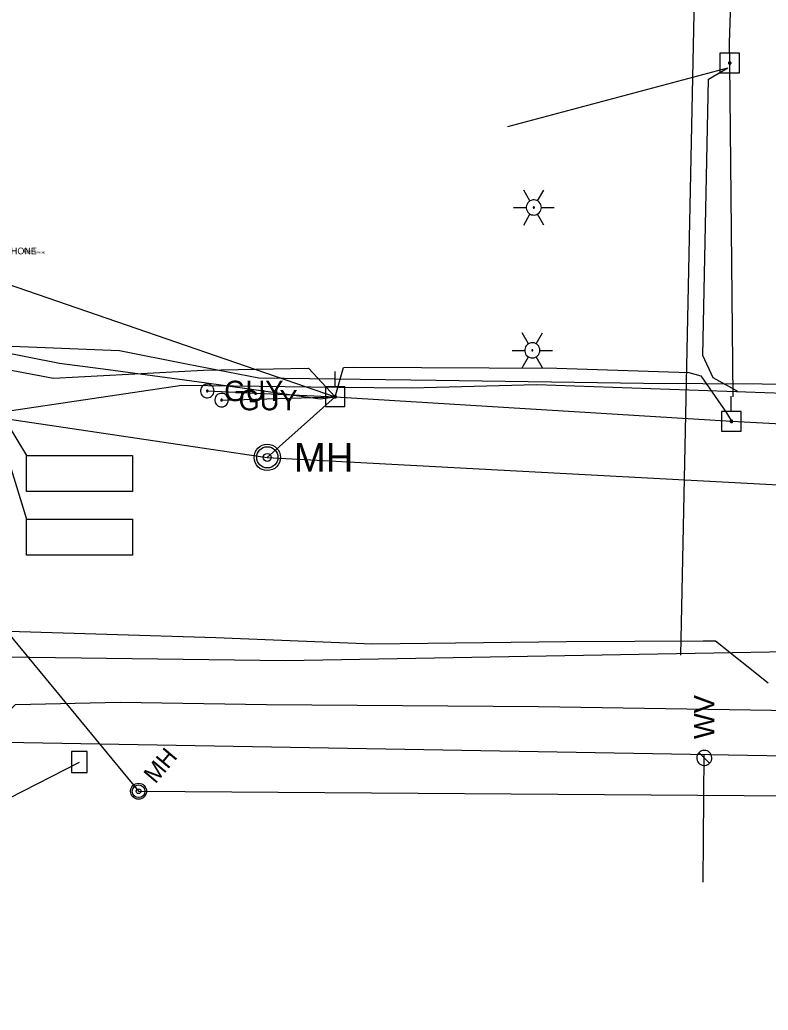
# Model space of a CAD drawing. Extents: x 596028 to 606371, y 330010 to 403088.
# Drawn here: x 605117.4 to 605258.6, y 332615.5 to 332802.3 of the extents above; entities that cross this region are included whole.
import ezdxf

# ---------------------------------------------------------------- set-up
doc = ezdxf.new("R2010")
doc.units = 0
for name, color, linetype in [('Default', 7, 'Continuous'), ('E_LTG', 7, 'Continuous'), ('E_SIG_Loops', 7, 'Continuous'), ('E_UTL_E', 7, 'Continuous'), ('E_UTL_E_UG', 7, 'Continuous'), ('E_UTL_EGuyWire', 7, 'Continuous'), ('E_UTL_EPowerPole', 7, 'Continuous'), ('E_UTL_FO_UG_MCI', 7, 'Continuous'), ('E_UTL_FO_UG_MWFN', 7, 'Continuous'), ('E_UTL_G_UG', 7, 'Continuous'), ('E_UTL_Overhead', 7, 'Continuous'), ('E_UTL_SAN_MH', 7, 'Continuous'), ('E_UTL_SAN_UG', 7, 'Continuous'), ('E_UTL_T', 7, 'Continuous'), ('E_UTL_T_UG', 7, 'Continuous'), ('E_UTL_TV_UG', 7, 'Continuous'), ('E_UTL_W', 7, 'Continuous'), ('E_UTL_W_UG', 7, 'Continuous')]:
    doc.layers.add(name, color=color, linetype=linetype)

# ---------------------------------------------------------------- blocks, each defined once
blk = doc.blocks.new('MH')
at = {"layer": 'Default'}
for radius in [15.2, 12.2, 4.57]:
    blk.add_circle((0, 0), radius, dxfattribs=at)
blk.add_text('MH', height=32.92, dxfattribs=at).set_placement((30.5, -16.5))

msp = doc.modelspace()

# ---------------------------------------------------------------- linework, layer by layer
at = {"layer": 'E_LTG'}
for points in [[(605213.67, 332768.13), (605212.48, 332770.19)], [(605215.1, 332768.13), (605216.29, 332770.19)], [(605215.82, 332766.89), (605215.79, 332767.16), (605215.71, 332767.42), (605215.59, 332767.67), (605215.42, 332767.88), (605215.22, 332768.06), (605214.98, 332768.19), (605214.72, 332768.28), (605214.45, 332768.32), (605214.18, 332768.31), (605213.92, 332768.24), (605213.67, 332768.13), (605213.45, 332767.97), (605213.26, 332767.78), (605213.12, 332767.55), (605213.02, 332767.3), (605212.96, 332767.03), (605212.96, 332766.76), (605213.02, 332766.49), (605213.12, 332766.24), (605213.26, 332766.01), (605213.45, 332765.81), (605213.67, 332765.66), (605213.92, 332765.54), (605214.18, 332765.48), (605214.45, 332765.47), (605214.72, 332765.5), (605214.98, 332765.59), (605215.22, 332765.73), (605215.42, 332765.91), (605215.59, 332766.12), (605215.71, 332766.36), (605215.79, 332766.62), (605215.82, 332766.89)], [(605215.82, 332766.89), (605215.79, 332767.16), (605215.71, 332767.42), (605215.59, 332767.67), (605215.42, 332767.88), (605215.22, 332768.06), (605214.98, 332768.19), (605214.72, 332768.28), (605214.45, 332768.32), (605214.18, 332768.31), (605213.92, 332768.24), (605213.67, 332768.13), (605213.45, 332767.97), (605213.26, 332767.78), (605213.12, 332767.55), (605213.02, 332767.3), (605212.96, 332767.03), (605212.96, 332766.76), (605213.02, 332766.49), (605213.12, 332766.24), (605213.26, 332766.01), (605213.45, 332765.81), (605213.67, 332765.66), (605213.92, 332765.54), (605214.18, 332765.48), (605214.45, 332765.47), (605214.72, 332765.5), (605214.98, 332765.59), (605215.22, 332765.73), (605215.42, 332765.91), (605215.59, 332766.12), (605215.71, 332766.36), (605215.79, 332766.62), (605215.82, 332766.89)], [(605215.82, 332766.89), (605215.79, 332767.16), (605215.71, 332767.42), (605215.59, 332767.67), (605215.42, 332767.88), (605215.22, 332768.06), (605214.98, 332768.19), (605214.72, 332768.28), (605214.45, 332768.32), (605214.18, 332768.31), (605213.92, 332768.24), (605213.67, 332768.13), (605213.45, 332767.97), (605213.26, 332767.78), (605213.12, 332767.55), (605213.02, 332767.3), (605212.96, 332767.03), (605212.96, 332766.76), (605213.02, 332766.49), (605213.12, 332766.24), (605213.26, 332766.01), (605213.45, 332765.81), (605213.67, 332765.66), (605213.92, 332765.54), (605214.18, 332765.48), (605214.45, 332765.47), (605214.72, 332765.5), (605214.98, 332765.59), (605215.22, 332765.73), (605215.42, 332765.91), (605215.59, 332766.12), (605215.71, 332766.36), (605215.79, 332766.62), (605215.82, 332766.89)], [(605210.58, 332766.89), (605212.96, 332766.89)], [(605214.51, 332766.89), (605214.5, 332766.92), (605214.5, 332766.94), (605214.49, 332766.96), (605214.47, 332766.98), (605214.46, 332766.99), (605214.44, 332767), (605214.42, 332767.01), (605214.39, 332767.01), (605214.37, 332767.01), (605214.35, 332767.01), (605214.33, 332767), (605214.31, 332766.98), (605214.29, 332766.97), (605214.28, 332766.95), (605214.27, 332766.93), (605214.27, 332766.9), (605214.27, 332766.88), (605214.27, 332766.86), (605214.28, 332766.84), (605214.29, 332766.82), (605214.31, 332766.8), (605214.33, 332766.79), (605214.35, 332766.78), (605214.37, 332766.78), (605214.39, 332766.77), (605214.42, 332766.78), (605214.44, 332766.78), (605214.46, 332766.8), (605214.47, 332766.81), (605214.49, 332766.83), (605214.5, 332766.85), (605214.5, 332766.87), (605214.51, 332766.89)], [(605215.82, 332766.89), (605218.2, 332766.89)], [(605212.48, 332763.59), (605213.67, 332765.66)], [(605216.29, 332763.59), (605215.1, 332765.66)], [(605213.39, 332741.19), (605212.2, 332743.25)], [(605214.82, 332741.19), (605216.01, 332743.25)], [(605210.3, 332739.95), (605212.68, 332739.95)], [(605215.54, 332739.95), (605215.51, 332740.22), (605215.43, 332740.48), (605215.31, 332740.72), (605215.14, 332740.94), (605214.94, 332741.11), (605214.7, 332741.25), (605214.44, 332741.34), (605214.18, 332741.38), (605213.9, 332741.36), (605213.64, 332741.3), (605213.39, 332741.19), (605213.17, 332741.03), (605212.98, 332740.83), (605212.84, 332740.6), (605212.74, 332740.35), (605212.69, 332740.08), (605212.69, 332739.81), (605212.74, 332739.55), (605212.84, 332739.29), (605212.98, 332739.07), (605213.17, 332738.87), (605213.39, 332738.71), (605213.64, 332738.6), (605213.9, 332738.53), (605214.18, 332738.52), (605214.44, 332738.56), (605214.7, 332738.65), (605214.94, 332738.78), (605215.14, 332738.96), (605215.31, 332739.18), (605215.43, 332739.42), (605215.51, 332739.68), (605215.54, 332739.95)], [(605215.54, 332739.95), (605215.51, 332740.22), (605215.43, 332740.48), (605215.31, 332740.72), (605215.14, 332740.94), (605214.94, 332741.11), (605214.7, 332741.25), (605214.44, 332741.34), (605214.18, 332741.38), (605213.9, 332741.36), (605213.64, 332741.3), (605213.39, 332741.19), (605213.17, 332741.03), (605212.98, 332740.83), (605212.84, 332740.6), (605212.74, 332740.35), (605212.69, 332740.08), (605212.69, 332739.81), (605212.74, 332739.55), (605212.84, 332739.29), (605212.98, 332739.07), (605213.17, 332738.87), (605213.39, 332738.71), (605213.64, 332738.6), (605213.9, 332738.53), (605214.18, 332738.52), (605214.44, 332738.56), (605214.7, 332738.65), (605214.94, 332738.78), (605215.14, 332738.96), (605215.31, 332739.18), (605215.43, 332739.42), (605215.51, 332739.68), (605215.54, 332739.95)], [(605215.54, 332739.95), (605215.51, 332740.22), (605215.43, 332740.48), (605215.31, 332740.72), (605215.14, 332740.94), (605214.94, 332741.11), (605214.7, 332741.25), (605214.44, 332741.34), (605214.18, 332741.38), (605213.9, 332741.36), (605213.64, 332741.3), (605213.39, 332741.19), (605213.17, 332741.03), (605212.98, 332740.83), (605212.84, 332740.6), (605212.74, 332740.35), (605212.69, 332740.08), (605212.69, 332739.81), (605212.74, 332739.55), (605212.84, 332739.29), (605212.98, 332739.07), (605213.17, 332738.87), (605213.39, 332738.71), (605213.64, 332738.6), (605213.9, 332738.53), (605214.18, 332738.52), (605214.44, 332738.56), (605214.7, 332738.65), (605214.94, 332738.78), (605215.14, 332738.96), (605215.31, 332739.18), (605215.43, 332739.42), (605215.51, 332739.68), (605215.54, 332739.95)], [(605214.23, 332739.95), (605214.22, 332739.97), (605214.22, 332739.99), (605214.21, 332740.01), (605214.19, 332740.03), (605214.18, 332740.05), (605214.16, 332740.06), (605214.14, 332740.06), (605214.11, 332740.07), (605214.09, 332740.07), (605214.07, 332740.06), (605214.05, 332740.05), (605214.03, 332740.04), (605214.01, 332740.02), (605214, 332740), (605213.99, 332739.98), (605213.99, 332739.96), (605213.99, 332739.94), (605213.99, 332739.92), (605214, 332739.89), (605214.01, 332739.88), (605214.03, 332739.86), (605214.05, 332739.85), (605214.07, 332739.84), (605214.09, 332739.83), (605214.11, 332739.83), (605214.14, 332739.83), (605214.16, 332739.84), (605214.18, 332739.85), (605214.19, 332739.87), (605214.21, 332739.88), (605214.22, 332739.9), (605214.22, 332739.93), (605214.23, 332739.95)], [(605215.54, 332739.95), (605217.92, 332739.95)], [(605212.2, 332736.65), (605213.39, 332738.71)], [(605216.01, 332736.65), (605214.82, 332738.71)]]:
    msp.add_lwpolyline(points, dxfattribs=at)
at = {"layer": 'E_SIG_Loops'}
for q in [(605118.72, 332720.09), (605118.72, 332708.09)]:
    msp.add_line((605111.16, 332732.52), q, dxfattribs=at)
for points in [[(605138.72, 332713.34), (605118.72, 332713.34), (605118.72, 332720.09), (605138.72, 332720.09), (605138.72, 332713.34)], [(605138.72, 332701.34), (605118.72, 332701.34), (605118.72, 332708.09), (605138.72, 332708.09), (605138.72, 332701.34)]]:
    msp.add_lwpolyline(points, dxfattribs=at)
at = {"layer": 'E_UTL_E_UG'}
for q in [(605176.94, 332731.2), (605466.18, 332703.6)]:
    msp.add_line((605164.12, 332719.76), q, dxfattribs=at)
msp.add_lwpolyline([(605006.49, 332733.09), (605075.22, 332732.97), (605164.12, 332719.76)], dxfattribs=at)
at = {"layer": 'E_UTL_EGuyWire'}
for p in [(605152.8, 332732.29), (605155.49, 332730.56)]:
    msp.add_line(p, (605176.94, 332731.2), dxfattribs=at)
for points in [[(605154.08, 332732.29), (605154.06, 332732.54), (605153.99, 332732.77), (605153.88, 332732.99), (605153.73, 332733.18), (605153.54, 332733.34), (605153.33, 332733.46), (605153.1, 332733.54), (605152.86, 332733.57), (605152.62, 332733.56), (605152.38, 332733.51), (605152.16, 332733.4), (605151.96, 332733.26), (605151.79, 332733.09), (605151.66, 332732.88), (605151.57, 332732.65), (605151.52, 332732.41), (605151.52, 332732.17), (605151.57, 332731.93), (605151.66, 332731.7), (605151.79, 332731.5), (605151.96, 332731.32), (605152.16, 332731.18), (605152.38, 332731.08), (605152.62, 332731.02), (605152.86, 332731.01), (605153.1, 332731.05), (605153.33, 332731.13), (605153.54, 332731.25), (605153.73, 332731.41), (605153.88, 332731.6), (605153.99, 332731.82), (605154.06, 332732.05), (605154.08, 332732.29)], [(605152.96, 332732.29), (605152.96, 332732.32), (605152.95, 332732.35), (605152.93, 332732.38), (605152.92, 332732.4), (605152.89, 332732.42), (605152.87, 332732.44), (605152.84, 332732.45), (605152.81, 332732.45), (605152.78, 332732.45), (605152.75, 332732.44), (605152.72, 332732.43), (605152.69, 332732.41), (605152.67, 332732.39), (605152.66, 332732.37), (605152.65, 332732.34), (605152.64, 332732.31), (605152.64, 332732.28), (605152.65, 332732.25), (605152.66, 332732.22), (605152.67, 332732.19), (605152.69, 332732.17), (605152.72, 332732.15), (605152.75, 332732.14), (605152.78, 332732.13), (605152.81, 332732.13), (605152.84, 332732.14), (605152.87, 332732.15), (605152.89, 332732.16), (605152.92, 332732.18), (605152.93, 332732.21), (605152.95, 332732.23), (605152.96, 332732.26), (605152.96, 332732.29)], [(605156.77, 332730.56), (605156.75, 332730.8), (605156.68, 332731.04), (605156.57, 332731.26), (605156.42, 332731.45), (605156.23, 332731.61), (605156.02, 332731.73), (605155.79, 332731.81), (605155.55, 332731.84), (605155.31, 332731.83), (605155.07, 332731.77), (605154.85, 332731.67), (605154.65, 332731.53), (605154.48, 332731.36), (605154.35, 332731.15), (605154.26, 332730.92), (605154.21, 332730.68), (605154.21, 332730.44), (605154.26, 332730.2), (605154.35, 332729.97), (605154.48, 332729.77), (605154.65, 332729.59), (605154.85, 332729.45), (605155.07, 332729.35), (605155.31, 332729.29), (605155.55, 332729.28), (605155.79, 332729.31), (605156.02, 332729.39), (605156.23, 332729.52), (605156.42, 332729.68), (605156.57, 332729.87), (605156.68, 332730.09), (605156.75, 332730.32), (605156.77, 332730.56)], [(605155.65, 332730.56), (605155.65, 332730.59), (605155.64, 332730.62), (605155.62, 332730.65), (605155.6, 332730.67), (605155.58, 332730.69), (605155.55, 332730.71), (605155.53, 332730.72), (605155.5, 332730.72), (605155.47, 332730.72), (605155.44, 332730.71), (605155.41, 332730.7), (605155.38, 332730.68), (605155.36, 332730.66), (605155.35, 332730.64), (605155.33, 332730.61), (605155.33, 332730.58), (605155.33, 332730.55), (605155.33, 332730.52), (605155.35, 332730.49), (605155.36, 332730.46), (605155.38, 332730.44), (605155.41, 332730.42), (605155.44, 332730.41), (605155.47, 332730.4), (605155.5, 332730.4), (605155.53, 332730.41), (605155.55, 332730.42), (605155.58, 332730.43), (605155.6, 332730.45), (605155.62, 332730.48), (605155.64, 332730.5), (605155.65, 332730.53), (605155.65, 332730.56)]]:
    msp.add_lwpolyline(points, dxfattribs=at)
at = {"layer": 'E_UTL_EPowerPole'}
for points in [[(605251.32, 332795.99), (605251.32, 332798.89)], [(605253.16, 332795.99), (605249.48, 332795.99)], [(605249.48, 332795.99), (605249.48, 332792.29)], [(605253.16, 332792.29), (605253.16, 332795.99)], [(605251.59, 332794.14), (605251.59, 332794.19), (605251.57, 332794.23), (605251.55, 332794.27), (605251.52, 332794.31), (605251.49, 332794.34), (605251.45, 332794.36), (605251.41, 332794.37), (605251.36, 332794.38), (605251.32, 332794.38), (605251.27, 332794.37), (605251.23, 332794.35), (605251.2, 332794.32), (605251.16, 332794.29), (605251.14, 332794.25), (605251.12, 332794.21), (605251.11, 332794.17), (605251.11, 332794.12), (605251.12, 332794.08), (605251.14, 332794.03), (605251.16, 332794), (605251.2, 332793.96), (605251.23, 332793.94), (605251.27, 332793.92), (605251.32, 332793.91), (605251.36, 332793.9), (605251.41, 332793.91), (605251.45, 332793.93), (605251.49, 332793.95), (605251.52, 332793.98), (605251.55, 332794.01), (605251.57, 332794.05), (605251.59, 332794.1), (605251.59, 332794.14)], [(605249.48, 332792.29), (605253.16, 332792.29)], [(605176.91, 332733.04), (605176.91, 332735.95)], [(605178.75, 332733.04), (605175.07, 332733.04)], [(605175.07, 332733.04), (605175.07, 332729.35)], [(605178.75, 332729.35), (605178.75, 332733.04)], [(605177.18, 332731.2), (605177.18, 332731.25), (605177.16, 332731.29), (605177.14, 332731.33), (605177.11, 332731.37), (605177.08, 332731.4), (605177.04, 332731.42), (605177, 332731.43), (605176.95, 332731.44), (605176.91, 332731.44), (605176.86, 332731.43), (605176.82, 332731.41), (605176.78, 332731.38), (605176.75, 332731.35), (605176.73, 332731.31), (605176.71, 332731.27), (605176.7, 332731.22), (605176.7, 332731.18), (605176.71, 332731.13), (605176.73, 332731.09), (605176.75, 332731.05), (605176.78, 332731.02), (605176.82, 332730.99), (605176.86, 332730.98), (605176.91, 332730.96), (605176.95, 332730.96), (605177, 332730.97), (605177.04, 332730.98), (605177.08, 332731.01), (605177.11, 332731.04), (605177.14, 332731.07), (605177.16, 332731.11), (605177.18, 332731.16), (605177.18, 332731.2)], [(605251.63, 332728.4), (605251.63, 332731.31)], [(605175.07, 332729.35), (605178.75, 332729.35)], [(605253.48, 332728.4), (605249.79, 332728.4)], [(605249.79, 332728.4), (605249.79, 332724.71)], [(605251.91, 332726.56), (605251.9, 332726.6), (605251.89, 332726.65), (605251.87, 332726.69), (605251.84, 332726.72), (605251.8, 332726.75), (605251.77, 332726.77), (605251.72, 332726.79), (605251.68, 332726.79), (605251.63, 332726.79), (605251.59, 332726.78), (605251.55, 332726.76), (605251.51, 332726.74), (605251.48, 332726.7), (605251.45, 332726.67), (605251.44, 332726.62), (605251.43, 332726.58), (605251.43, 332726.53), (605251.44, 332726.49), (605251.45, 332726.45), (605251.48, 332726.41), (605251.51, 332726.38), (605251.55, 332726.35), (605251.59, 332726.33), (605251.63, 332726.32), (605251.68, 332726.32), (605251.72, 332726.32), (605251.77, 332726.34), (605251.8, 332726.36), (605251.84, 332726.39), (605251.87, 332726.43), (605251.89, 332726.47), (605251.9, 332726.51), (605251.91, 332726.56)], [(605253.48, 332724.71), (605253.48, 332728.4)], [(605249.79, 332724.71), (605253.48, 332724.71)]]:
    msp.add_lwpolyline(points, dxfattribs=at)
at = {"layer": 'E_UTL_FO_UG_MCI'}
for points in [[(604825.96, 332739.78), (604920.61, 332734.36), (604934.01, 332733.31), (604965.47, 332732.98), (605000.46, 332732.52), (605007.07, 332734.66), (605013.89, 332743.48), (605017, 332744.16), (605019.17, 332746.55), (605020.12, 332744.84), (605024.63, 332744.84), (605063.91, 332747.38), (605094.59, 332749.32), (605105.01, 332741.19), (605136.25, 332739.94), (605148.9, 332737.41), (605162.55, 332734.79), (605195.98, 332734.31), (605235.11, 332733.74)], [(605235.11, 332733.74), (605492.46, 332732.33), (605498.38, 332739.75)]]:
    msp.add_lwpolyline(points, dxfattribs=at)
at = {"layer": 'E_UTL_FO_UG_MWFN'}
msp.add_lwpolyline([(605015.05, 332668.24), (605020.63, 332655.48), (605115.41, 332655.48), (605128.67, 332662.3)], dxfattribs=at)
msp.add_lwpolyline([(605127.17, 332660.3), (605130.17, 332660.3), (605130.17, 332664.3), (605127.17, 332664.3)], close=True, dxfattribs=at)
at = {"layer": 'E_UTL_G_UG'}
msp.add_line((605242.14, 332682.48), (605250.58, 333096.27), dxfattribs=at)
for points in [[(605105.02, 332679.39), (605106.15, 332682.57), (605109.07, 332687.18), (605154.43, 332685.81), (605183.98, 332684.57), (605220.55, 332685.01), (605246.35, 332685.13)], [(605246.35, 332685.13), (605248.65, 332685.13), (605258.6, 332677.26)], [(604999.13, 332234.39), (604999.86, 332312.33), (605000.09, 332338.31), (605000.11, 332381.53), (605000.58, 332421.33), (605001.25, 332517.82), (605001.72, 332543.05), (605001.99, 332582.9), (605009.14, 332588.51), (605017.08, 332595.02), (605025.17, 332603.98), (605053.2, 332636.73), (605068.82, 332651.42), (605069.91, 332651.64), (605092.37, 332651), (605098.99, 332656), (605103.96, 332660.87), (605106.76, 332663.11), (605116.6, 332673.18), (605136.39, 332673.6), (605163.97, 332673.14), (605215.25, 332672.77), (605447.16, 332669.14)]]:
    msp.add_lwpolyline(points, dxfattribs=at)
at = {"layer": 'E_UTL_Overhead'}
msp.add_line((605209.48, 332782.17), (605251.01, 332793.26), dxfattribs=at)
for points in [[(605251.35, 332794.14), (605251.32, 332797.87), (605254.28, 332888.93), (605255.36, 332982.6), (605256.54, 333101.39), (605259.23, 333266.42), (605263.85, 333423.49), (605264.54, 333496.55), (605268.31, 333630.66)], [(605251.97, 332731.16), (605251.35, 332794.14)], [(605176.94, 332731.2), (605251.67, 332726.56), (605281.19, 332725), (605445.44, 332722.04)]]:
    msp.add_lwpolyline(points, dxfattribs=at)
at = {"layer": 'E_UTL_SAN_MH'}
for radius in [1.5, 1.2, 0.45]:
    msp.add_circle((605139.84, 332656.79), radius, dxfattribs=at)
at = {"layer": 'E_UTL_SAN_UG'}
for p, q in [((605095.5, 332710.46), (605139.84, 332656.79)), ((605139.84, 332656.79), (605290.54, 332655.71))]:
    msp.add_line(p, q, dxfattribs=at)
at = {"layer": 'E_UTL_T'}
msp.add_lwpolyline([(605107.51, 332755.1), (605176.94, 332731.2)], dxfattribs=at)
at = {"layer": 'E_UTL_T_UG'}
for points in [[(605252.89, 332732.19), (605248.22, 332734.74), (605246.29, 332738.95), (605247.35, 332791.11), (605251.01, 332793.26)], [(605114.2, 332728.34), (605148.01, 332733.35), (605177.23, 332732.99), (605191.32, 332732.89), (605214.93, 332733.52), (605275.9, 332731.38), (605316.06, 332730.67), (605353.02, 332730.35), (605397.93, 332729.76), (605398, 332729.79), (605441.12, 332728.95), (605479.18, 332728.65), (605509.36, 332728.83)]]:
    msp.add_lwpolyline(points, dxfattribs=at)
at = {"layer": 'E_UTL_TV_UG'}
for points in [[(605094.66, 332749.57), (605097.81, 332743.85), (605105.06, 332738.21), (605123.76, 332734.73), (605152.11, 332736.19), (605171.9, 332736.6), (605176.94, 332731.2)], [(605107.38, 332741), (605124.95, 332737.5), (605134.08, 332736.35), (605152.24, 332733.9), (605174.08, 332730.78), (605176.94, 332731.2)], [(605176.94, 332731.2), (605178.51, 332736.73), (605180.44, 332736.77), (605218.75, 332736.61), (605243.65, 332735.76), (605245.89, 332735.14), (605250.73, 332728.15), (605251.67, 332726.56)]]:
    msp.add_lwpolyline(points, dxfattribs=at)
at = {"layer": 'E_UTL_W'}
for points in [[(605246.55, 332664.5), (605246.28, 332664.48), (605246.02, 332664.4), (605245.78, 332664.28), (605245.56, 332664.11), (605245.38, 332663.9), (605245.25, 332663.67), (605245.16, 332663.41), (605245.12, 332663.14), (605245.13, 332662.87), (605245.2, 332662.61), (605245.31, 332662.36), (605245.47, 332662.14), (605245.66, 332661.95), (605245.89, 332661.81), (605246.14, 332661.71), (605246.41, 332661.66), (605246.68, 332661.66), (605246.95, 332661.71), (605247.2, 332661.81), (605247.43, 332661.95), (605247.62, 332662.14), (605247.78, 332662.36), (605247.89, 332662.61), (605247.96, 332662.87), (605247.97, 332663.14), (605247.93, 332663.41), (605247.84, 332663.67), (605247.71, 332663.9), (605247.53, 332664.11), (605247.32, 332664.28), (605247.08, 332664.4), (605246.82, 332664.48), (605246.55, 332664.5)], [(605247.55, 332662.07), (605245.54, 332664.08)]]:
    msp.add_lwpolyline(points, dxfattribs=at)
at = {"layer": 'E_UTL_W_UG'}
for points in [[(604753.86, 332778.54), (604834.37, 332685.14), (604847.57, 332682.96), (604869.92, 332684.91), (604879.8, 332686.08), (604902.06, 332691.47), (604979.47, 332683.9), (605167.57, 332681.44), (605290.47, 332683.62), (605413.37, 332685.79)], [(605100.16, 332666.29), (605269.09, 332663.36), (605338.46, 332662.27)], [(605246.34, 332639.62), (605246.55, 332663.75)]]:
    msp.add_lwpolyline(points, dxfattribs=at)

# ---------------------------------------------------------------- block references
at = {"layer": 'E_UTL_E', "xscale": 0.16404166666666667, "yscale": 0.16404166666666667}
msp.add_blockref('MH', (605164.12, 332719.76), dxfattribs=at)

# ---------------------------------------------------------------- texts
at = {"layer": 'E_UTL_EGuyWire'}
for p in [(605156.01, 332730.37), (605158.7, 332728.64)]:
    msp.add_text('GUY', height=3.85, dxfattribs=at).set_placement(p)
at = {"layer": 'E_UTL_SAN_MH'}
msp.add_text('MH', height=3.24, rotation=50.0714, dxfattribs=at).set_placement((605143.01, 332658.05))
at = {"layer": 'E_UTL_T'}
for s, height, p in [('PHONE', 1.267, (605114.62, 332758.06)), ('501201234', 0.3, (605118.22, 332758.86)), ('649.942', 0.3, (605118.21, 332758.55)), ('TB0 BOOTH PHONE', 0.3, (605118.24, 332758.25))]:
    msp.add_text(s, height=height, dxfattribs=at).set_placement(p)
at = {"layer": 'E_UTL_W'}
msp.add_text('WV', height=3.85, rotation=90, dxfattribs=at).set_placement((605248.47, 332666.64))

doc.saveas('drawing.dxf')
